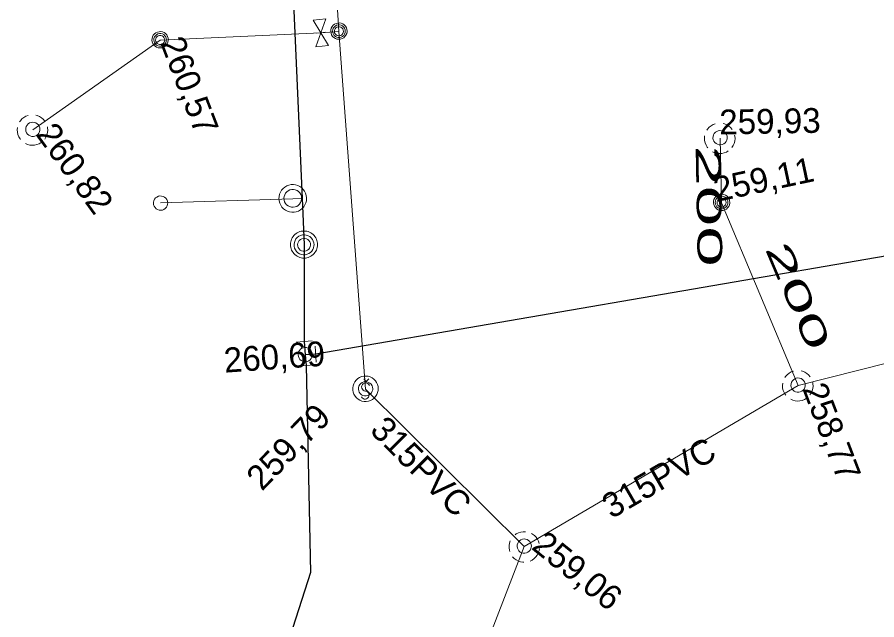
# Model space of a CAD drawing. Extents: x -732096 to -731933, y -1048703 to -1047964.
# Drawn here: x -732042.72 to -732014.98, y -1048007.32 to -1047987.86 of the extents above; entities that cross this region are included whole.
import ezdxf

# ---------------------------------------------------------------- set-up
doc = ezdxf.new("R2010")
doc.units = 0
doc.header["$LTSCALE"] = 0.32
doc.layers.add('1', color=7, linetype='Continuous')
for name, color, linetype, lineweight in [('18', 7, 'Continuous', 13), ('20', 7, 'Continuous', 13), ('21', 7, 'Continuous', 13), ('49', 7, 'Continuous', 13), ('50', 7, 'Continuous', 13), ('8', 7, 'Continuous', 13)]:
    doc.layers.add(name, color=color, linetype=linetype, lineweight=lineweight)

msp = doc.modelspace()

# ---------------------------------------------------------------- linework, layer by layer
at = {"layer": '18'}
for q in [(-732033.071, -1047988.374), (-732032.773, -1047988.343)]:
    msp.add_line((-732032.922, -1047988.359), q, dxfattribs=at)
for points in [[(-732032.671, -1047988.769), (-732033.173, -1047987.949), (-732032.761, -1047987.906), (-732033.083, -1047988.812)], [(-732032.076, -1047988.307), (-732032.081, -1047988.251), (-732032.098, -1047988.198), (-732032.127, -1047988.149), (-732032.166, -1047988.108), (-732032.212, -1047988.076), (-732032.264, -1047988.054), (-732032.319, -1047988.043), (-732032.375, -1047988.045), (-732032.429, -1047988.058), (-732032.48, -1047988.083), (-732032.525, -1047988.118), (-732032.561, -1047988.161), (-732032.586, -1047988.211), (-732032.601, -1047988.266), (-732032.603, -1047988.322), (-732032.595, -1047988.377), (-732032.574, -1047988.43), (-732032.543, -1047988.476), (-732032.502, -1047988.515), (-732032.455, -1047988.545), (-732032.402, -1047988.564), (-732032.346, -1047988.571), (-732032.289, -1047988.567), (-732032.235, -1047988.55), (-732032.186, -1047988.523), (-732032.145, -1047988.485), (-732032.112, -1047988.44), (-732032.088, -1047988.389), (-732032.076, -1047988.334)], [(-732032.135, -1047988.31), (-732032.141, -1047988.261), (-732032.159, -1047988.215), (-732032.186, -1047988.174), (-732032.223, -1047988.141), (-732032.267, -1047988.119), (-732032.316, -1047988.107), (-732032.365, -1047988.107), (-732032.413, -1047988.119), (-732032.456, -1047988.142), (-732032.494, -1047988.175), (-732032.522, -1047988.216), (-732032.539, -1047988.263), (-732032.544, -1047988.312), (-732032.538, -1047988.361), (-732032.52, -1047988.407), (-732032.492, -1047988.447), (-732032.455, -1047988.48), (-732032.411, -1047988.502), (-732032.362, -1047988.514), (-732032.313, -1047988.513), (-732032.265, -1047988.501), (-732032.222, -1047988.477), (-732032.184, -1047988.444), (-732032.157, -1047988.403), (-732032.141, -1047988.356)], [(-732032.194, -1047988.314), (-732032.2, -1047988.272), (-732032.217, -1047988.234), (-732032.245, -1047988.203), (-732032.279, -1047988.18), (-732032.32, -1047988.169), (-732032.362, -1047988.169), (-732032.402, -1047988.181), (-732032.436, -1047988.204), (-732032.463, -1047988.236), (-732032.48, -1047988.274), (-732032.485, -1047988.315), (-732032.48, -1047988.357), (-732032.462, -1047988.394), (-732032.434, -1047988.426), (-732032.397, -1047988.448), (-732032.358, -1047988.459), (-732032.316, -1047988.458), (-732032.276, -1047988.445), (-732032.242, -1047988.422), (-732032.215, -1047988.389), (-732032.199, -1047988.351)], [(-732037.845, -1047988.587), (-732037.851, -1047988.531), (-732037.868, -1047988.478), (-732037.897, -1047988.429), (-732037.935, -1047988.388), (-732037.981, -1047988.356), (-732038.033, -1047988.334), (-732038.088, -1047988.323), (-732038.144, -1047988.325), (-732038.199, -1047988.338), (-732038.25, -1047988.363), (-732038.294, -1047988.398), (-732038.33, -1047988.441), (-732038.355, -1047988.491), (-732038.37, -1047988.546), (-732038.373, -1047988.602), (-732038.364, -1047988.657), (-732038.343, -1047988.71), (-732038.312, -1047988.756), (-732038.272, -1047988.795), (-732038.224, -1047988.825), (-732038.171, -1047988.844), (-732038.115, -1047988.851), (-732038.059, -1047988.847), (-732038.005, -1047988.83), (-732037.956, -1047988.803), (-732037.914, -1047988.765), (-732037.881, -1047988.72), (-732037.858, -1047988.669), (-732037.846, -1047988.614)], [(-732037.904, -1047988.59), (-732037.91, -1047988.541), (-732037.928, -1047988.495), (-732037.956, -1047988.454), (-732037.993, -1047988.421), (-732038.037, -1047988.399), (-732038.085, -1047988.387), (-732038.134, -1047988.387), (-732038.182, -1047988.399), (-732038.226, -1047988.422), (-732038.263, -1047988.455), (-732038.291, -1047988.496), (-732038.308, -1047988.543), (-732038.314, -1047988.592), (-732038.307, -1047988.641), (-732038.289, -1047988.687), (-732038.261, -1047988.727), (-732038.224, -1047988.76), (-732038.18, -1047988.782), (-732038.131, -1047988.794), (-732038.082, -1047988.793), (-732038.034, -1047988.781), (-732037.991, -1047988.757), (-732037.954, -1047988.724), (-732037.926, -1047988.683), (-732037.91, -1047988.636)], [(-732037.963, -1047988.594), (-732037.969, -1047988.552), (-732037.986, -1047988.514), (-732038.014, -1047988.483), (-732038.049, -1047988.46), (-732038.089, -1047988.449), (-732038.131, -1047988.449), (-732038.171, -1047988.461), (-732038.206, -1047988.484), (-732038.233, -1047988.516), (-732038.25, -1047988.554), (-732038.255, -1047988.595), (-732038.249, -1047988.637), (-732038.231, -1047988.674), (-732038.203, -1047988.706), (-732038.167, -1047988.728), (-732038.127, -1047988.739), (-732038.085, -1047988.738), (-732038.045, -1047988.725), (-732038.011, -1047988.702), (-732037.984, -1047988.669), (-732037.968, -1047988.631)], [(-732041.988, -1047991.479), (-732041.994, -1047991.427), (-732042.012, -1047991.377), (-732042.04, -1047991.333), (-732042.078, -1047991.296), (-732042.123, -1047991.269), (-732042.173, -1047991.253), (-732042.225, -1047991.248), (-732042.277, -1047991.255), (-732042.326, -1047991.274), (-732042.37, -1047991.304), (-732042.405, -1047991.343), (-732042.431, -1047991.388), (-732042.446, -1047991.439), (-732042.449, -1047991.491), (-732042.441, -1047991.543), (-732042.42, -1047991.591), (-732042.39, -1047991.634), (-732042.35, -1047991.669), (-732042.304, -1047991.693), (-732042.253, -1047991.707), (-732042.201, -1047991.709), (-732042.149, -1047991.699), (-732042.101, -1047991.677), (-732042.059, -1047991.645), (-732042.026, -1047991.605), (-732042.002, -1047991.558), (-732041.99, -1047991.507)], [(-732019.808, -1047991.749), (-732019.814, -1047991.697), (-732019.831, -1047991.647), (-732019.86, -1047991.603), (-732019.898, -1047991.566), (-732019.943, -1047991.539), (-732019.993, -1047991.523), (-732020.045, -1047991.518), (-732020.097, -1047991.525), (-732020.146, -1047991.544), (-732020.19, -1047991.574), (-732020.225, -1047991.613), (-732020.251, -1047991.658), (-732020.266, -1047991.709), (-732020.269, -1047991.761), (-732020.261, -1047991.813), (-732020.24, -1047991.861), (-732020.21, -1047991.904), (-732020.17, -1047991.939), (-732020.124, -1047991.963), (-732020.073, -1047991.977), (-732020.021, -1047991.979), (-732019.969, -1047991.969), (-732019.921, -1047991.947), (-732019.879, -1047991.915), (-732019.846, -1047991.875), (-732019.822, -1047991.828), (-732019.809, -1047991.777)], [(-732019.725, -1047993.837), (-732019.73, -1047993.781), (-732019.747, -1047993.728), (-732019.776, -1047993.679), (-732019.815, -1047993.638), (-732019.86, -1047993.606), (-732019.913, -1047993.584), (-732019.968, -1047993.573), (-732020.024, -1047993.575), (-732020.078, -1047993.588), (-732020.129, -1047993.613), (-732020.174, -1047993.648), (-732020.21, -1047993.691), (-732020.235, -1047993.741), (-732020.25, -1047993.796), (-732020.252, -1047993.852), (-732020.244, -1047993.907), (-732020.223, -1047993.96), (-732020.191, -1047994.006), (-732020.151, -1047994.045), (-732020.103, -1047994.075), (-732020.051, -1047994.094), (-732019.995, -1047994.101), (-732019.938, -1047994.097), (-732019.884, -1047994.08), (-732019.835, -1047994.053), (-732019.794, -1047994.015), (-732019.761, -1047993.97), (-732019.737, -1047993.919), (-732019.725, -1047993.864)], [(-732019.784, -1047993.84), (-732019.789, -1047993.791), (-732019.808, -1047993.745), (-732019.835, -1047993.704), (-732019.872, -1047993.671), (-732019.916, -1047993.649), (-732019.965, -1047993.637), (-732020.014, -1047993.637), (-732020.061, -1047993.649), (-732020.105, -1047993.672), (-732020.142, -1047993.705), (-732020.171, -1047993.746), (-732020.188, -1047993.793), (-732020.193, -1047993.842), (-732020.186, -1047993.891), (-732020.169, -1047993.937), (-732020.141, -1047993.977), (-732020.103, -1047994.01), (-732020.059, -1047994.032), (-732020.011, -1047994.044), (-732019.962, -1047994.043), (-732019.914, -1047994.031), (-732019.87, -1047994.007), (-732019.833, -1047993.974), (-732019.806, -1047993.933), (-732019.789, -1047993.886)], [(-732019.843, -1047993.844), (-732019.848, -1047993.802), (-732019.865, -1047993.764), (-732019.894, -1047993.733), (-732019.928, -1047993.71), (-732019.968, -1047993.699), (-732020.011, -1047993.699), (-732020.051, -1047993.711), (-732020.085, -1047993.734), (-732020.112, -1047993.766), (-732020.129, -1047993.804), (-732020.134, -1047993.845), (-732020.129, -1047993.887), (-732020.11, -1047993.924), (-732020.083, -1047993.956), (-732020.046, -1047993.978), (-732020.007, -1047993.989), (-732019.965, -1047993.988), (-732019.924, -1047993.975), (-732019.891, -1047993.952), (-732019.864, -1047993.919), (-732019.848, -1047993.881)], [(-732031.071, -1047999.857), (-732031.078, -1047999.787), (-732031.096, -1047999.719), (-732031.125, -1047999.655), (-732031.164, -1047999.597), (-732031.213, -1047999.547), (-732031.27, -1047999.505), (-732031.333, -1047999.474), (-732031.4, -1047999.454), (-732031.47, -1047999.445), (-732031.54, -1047999.449), (-732031.608, -1047999.464), (-732031.673, -1047999.491), (-732031.733, -1047999.529), (-732031.785, -1047999.576), (-732031.828, -1047999.631), (-732031.862, -1047999.693), (-732031.884, -1047999.76), (-732031.895, -1047999.829), (-732031.892, -1047999.899), (-732031.88, -1047999.968), (-732031.856, -1048000.034), (-732031.82, -1048000.095), (-732031.775, -1048000.148), (-732031.721, -1048000.194), (-732031.661, -1048000.229), (-732031.595, -1048000.254), (-732031.526, -1048000.267), (-732031.456, -1048000.268), (-732031.386, -1048000.257), (-732031.32, -1048000.235), (-732031.258, -1048000.201), (-732031.203, -1048000.158), (-732031.156, -1048000.106), (-732031.118, -1048000.046), (-732031.091, -1047999.981), (-732031.076, -1047999.913)], [(-732017.289, -1047999.739), (-732017.295, -1047999.687), (-732017.313, -1047999.637), (-732017.341, -1047999.593), (-732017.379, -1047999.556), (-732017.424, -1047999.529), (-732017.474, -1047999.513), (-732017.526, -1047999.508), (-732017.578, -1047999.515), (-732017.627, -1047999.534), (-732017.671, -1047999.564), (-732017.706, -1047999.603), (-732017.732, -1047999.648), (-732017.747, -1047999.699), (-732017.75, -1047999.751), (-732017.742, -1047999.803), (-732017.721, -1047999.851), (-732017.691, -1047999.894), (-732017.651, -1047999.929), (-732017.605, -1047999.953), (-732017.554, -1047999.967), (-732017.502, -1047999.969), (-732017.45, -1047999.959), (-732017.402, -1047999.937), (-732017.36, -1047999.905), (-732017.327, -1047999.865), (-732017.303, -1047999.818), (-732017.291, -1047999.767)], [(-732031.249, -1047999.859), (-732031.255, -1047999.807), (-732031.272, -1047999.757), (-732031.301, -1047999.713), (-732031.339, -1047999.676), (-732031.384, -1047999.649), (-732031.434, -1047999.633), (-732031.486, -1047999.628), (-732031.538, -1047999.635), (-732031.587, -1047999.654), (-732031.63, -1047999.684), (-732031.666, -1047999.723), (-732031.692, -1047999.768), (-732031.706, -1047999.819), (-732031.71, -1047999.871), (-732031.701, -1047999.923), (-732031.681, -1047999.971), (-732031.651, -1048000.014), (-732031.611, -1048000.049), (-732031.565, -1048000.073), (-732031.514, -1048000.087), (-732031.462, -1048000.089), (-732031.41, -1048000.079), (-732031.362, -1048000.057), (-732031.32, -1048000.025), (-732031.287, -1047999.985), (-732031.263, -1047999.938), (-732031.25, -1047999.887)], [(-732026.128, -1048004.939), (-732026.134, -1048004.887), (-732026.152, -1048004.837), (-732026.18, -1048004.793), (-732026.218, -1048004.756), (-732026.263, -1048004.729), (-732026.313, -1048004.713), (-732026.365, -1048004.708), (-732026.417, -1048004.715), (-732026.466, -1048004.734), (-732026.51, -1048004.764), (-732026.545, -1048004.803), (-732026.571, -1048004.848), (-732026.586, -1048004.899), (-732026.589, -1048004.951), (-732026.581, -1048005.003), (-732026.56, -1048005.051), (-732026.53, -1048005.094), (-732026.49, -1048005.129), (-732026.444, -1048005.153), (-732026.393, -1048005.167), (-732026.341, -1048005.169), (-732026.289, -1048005.159), (-732026.241, -1048005.137), (-732026.199, -1048005.105), (-732026.166, -1048005.065), (-732026.142, -1048005.018), (-732026.13, -1048004.967)]]:
    msp.add_lwpolyline(points, close=True, dxfattribs=at)
for points in [[(-732042.372, -1047991.027), (-732042.443, -1047991.055), (-732042.51, -1047991.094), (-732042.57, -1047991.142), (-732042.621, -1047991.199), (-732042.645, -1047991.233)], [(-732041.831, -1047991.21), (-732041.881, -1047991.152), (-732041.939, -1047991.102), (-732042.004, -1047991.061), (-732042.075, -1047991.032), (-732042.124, -1047991.018)], [(-732042.717, -1047991.419), (-732042.723, -1047991.496), (-732042.718, -1047991.573), (-732042.701, -1047991.648), (-732042.672, -1047991.719), (-732042.632, -1047991.785), (-732042.616, -1047991.807)], [(-732041.836, -1047991.796), (-732041.795, -1047991.731), (-732041.764, -1047991.661), (-732041.745, -1047991.586), (-732041.737, -1047991.51), (-732041.742, -1047991.433), (-732041.748, -1047991.398)], [(-732020.192, -1047991.297), (-732020.263, -1047991.325), (-732020.33, -1047991.364), (-732020.39, -1047991.412), (-732020.441, -1047991.469), (-732020.465, -1047991.503)], [(-732019.651, -1047991.48), (-732019.701, -1047991.422), (-732019.759, -1047991.372), (-732019.824, -1047991.331), (-732019.895, -1047991.302), (-732019.944, -1047991.288)], [(-732020.537, -1047991.689), (-732020.543, -1047991.766), (-732020.538, -1047991.843), (-732020.521, -1047991.918), (-732020.492, -1047991.989), (-732020.451, -1047992.055), (-732020.436, -1047992.077)], [(-732019.656, -1047992.066), (-732019.615, -1047992.001), (-732019.584, -1047991.931), (-732019.565, -1047991.856), (-732019.557, -1047991.78), (-732019.562, -1047991.703), (-732019.568, -1047991.668)], [(-732042.459, -1047991.936), (-732042.389, -1047991.967), (-732042.314, -1047991.986), (-732042.238, -1047991.993), (-732042.161, -1047991.988), (-732042.086, -1047991.971), (-732042.014, -1047991.943), (-732041.954, -1047991.908)], [(-732020.279, -1047992.206), (-732020.209, -1047992.237), (-732020.134, -1047992.256), (-732020.058, -1047992.263), (-732019.981, -1047992.258), (-732019.906, -1047992.241), (-732019.834, -1047992.213), (-732019.774, -1047992.178)], [(-732017.673, -1047999.287), (-732017.744, -1047999.315), (-732017.811, -1047999.354), (-732017.871, -1047999.402), (-732017.922, -1047999.459), (-732017.946, -1047999.493)], [(-732017.132, -1047999.47), (-732017.182, -1047999.412), (-732017.24, -1047999.362), (-732017.305, -1047999.321), (-732017.376, -1047999.292), (-732017.425, -1047999.278)], [(-732031.532, -1047999.537), (-732031.462, -1047999.624), (-732031.373, -1047999.535)], [(-732031.355, -1047999.749), (-732031.375, -1047999.715), (-732031.405, -1047999.689), (-732031.441, -1047999.673), (-732031.48, -1047999.669), (-732031.519, -1047999.676), (-732031.553, -1047999.695), (-732031.581, -1047999.723), (-732031.598, -1047999.758), (-732031.606, -1047999.797), (-732031.6, -1047999.836), (-732031.583, -1047999.871), (-732031.557, -1047999.9), (-732031.522, -1047999.92), (-732031.483, -1047999.929)], [(-732018.018, -1047999.679), (-732018.024, -1047999.756), (-732018.019, -1047999.833), (-732018.002, -1047999.908), (-732017.973, -1047999.979), (-732017.933, -1048000.045), (-732017.917, -1048000.067)], [(-732017.137, -1048000.056), (-732017.096, -1047999.991), (-732017.065, -1047999.921), (-732017.046, -1047999.846), (-732017.038, -1047999.77), (-732017.043, -1047999.693), (-732017.049, -1047999.658)], [(-732031.615, -1048000.116), (-732031.593, -1048000.149), (-732031.562, -1048000.174), (-732031.525, -1048000.188), (-732031.485, -1048000.191), (-732031.446, -1048000.182), (-732031.413, -1048000.162), (-732031.386, -1048000.132), (-732031.37, -1048000.096), (-732031.364, -1048000.057), (-732031.37, -1048000.018), (-732031.39, -1047999.983), (-732031.417, -1047999.955), (-732031.451, -1047999.936), (-732031.485, -1047999.929)], [(-732017.76, -1048000.196), (-732017.69, -1048000.227), (-732017.615, -1048000.246), (-732017.539, -1048000.253), (-732017.462, -1048000.248), (-732017.387, -1048000.231), (-732017.315, -1048000.203), (-732017.255, -1048000.168)], [(-732026.322, -1048004.473), (-732026.398, -1048004.474), (-732026.474, -1048004.486), (-732026.547, -1048004.509), (-732026.615, -1048004.544), (-732026.657, -1048004.573)], [(-732025.877, -1048004.855), (-732025.9, -1048004.781), (-732025.934, -1048004.713), (-732025.979, -1048004.65), (-732026.032, -1048004.594), (-732026.094, -1048004.549), (-732026.124, -1048004.531)], [(-732026.811, -1048004.768), (-732026.835, -1048004.84), (-732026.848, -1048004.917), (-732026.85, -1048004.993), (-732026.84, -1048005.069), (-732026.829, -1048005.109)], [(-732026.172, -1048005.421), (-732026.103, -1048005.387), (-732026.04, -1048005.342), (-732025.986, -1048005.289), (-732025.94, -1048005.227), (-732025.905, -1048005.159), (-732025.88, -1048005.086), (-732025.868, -1048005.017)], [(-732026.734, -1048005.284), (-732026.679, -1048005.339), (-732026.617, -1048005.385), (-732026.548, -1048005.42), (-732026.475, -1048005.444), (-732026.399, -1048005.456), (-732026.372, -1048005.458)]]:
    msp.add_lwpolyline(points, dxfattribs=at)
at = {"layer": '20'}
for points in [[(-732017.52, -1047999.75), (-732004.701, -1047996.513), (-731999.955, -1047995.314)], [(-732017.52, -1047999.75), (-732004.701, -1047996.513), (-731999.955, -1047995.314)], [(-732031.48, -1047999.87), (-732026.359, -1048004.95), (-732017.52, -1047999.75)], [(-732031.48, -1047999.87), (-732026.359, -1048004.95), (-732017.52, -1047999.75)], [(-732035.469, -1048028.56), (-732035.152, -1048027.738), (-732032.882, -1048021.854), (-732030.648, -1048016.063), (-732026.359, -1048004.95)], [(-732035.469, -1048028.56), (-732035.152, -1048027.738), (-732032.882, -1048021.854), (-732030.648, -1048016.063), (-732026.359, -1048004.95)]]:
    msp.add_lwpolyline(points, dxfattribs=at)
at = {"layer": '21'}
msp.add_lwpolyline([(-732033.777, -1047967.353), (-732033.19, -1047974.34), (-732032.34, -1047988.32), (-732031.48, -1047999.87)], dxfattribs=at)
msp.add_lwpolyline([(-732033.777, -1047967.353), (-732033.19, -1047974.34), (-732032.34, -1047988.32), (-732031.48, -1047999.87)], dxfattribs=at)
at = {"layer": '49'}
for p, q in [((-732020.039, -1047991.76), (-732019.989, -1047993.85)), ((-732020.039, -1047991.76), (-732019.989, -1047993.85)), ((-732019.989, -1047993.85), (-732017.52, -1047999.75)), ((-732019.989, -1047993.85), (-732017.52, -1047999.75))]:
    msp.add_line(p, q, dxfattribs=at)
at = {"layer": '50'}
for p, q in [((-732038.109, -1047988.6), (-732032.92, -1047988.36)), ((-732032.92, -1047988.36), (-732032.34, -1047988.32)), ((-732042.219, -1047991.49), (-732038.109, -1047988.6))]:
    msp.add_line(p, q, dxfattribs=at)
msp.add_lwpolyline([(-732042.219, -1047991.49), (-732038.109, -1047988.6), (-732032.92, -1047988.36), (-732032.34, -1047988.32)], dxfattribs=at)
at = {"layer": '8'}
for p, q in [((-732033.829, -1047993.72), (-732038.096, -1047993.852)), ((-732033.525, -1047993.715), (-732033.829, -1047993.72)), ((-732033.718, -1047998.35), (-732033.203, -1047998.31)), ((-732033.108, -1047998.48), (-732033.069, -1047998.995)), ((-732033.14, -1047999.088), (-732033.655, -1047999.131))]:
    msp.add_line(p, q, dxfattribs=at)
at = {"layer": '8', "lineweight": 25}
for p, q in [((-732033.46, -1047995.21), (-732033.46, -1047998.33)), ((-732014.03, -1047995.459), (-732033.089, -1047998.739)), ((-732033.46, -1047998.33), (-732033.427, -1047998.765)), ((-732033.089, -1047998.739), (-732033.427, -1047998.765)), ((-732033.427, -1047998.765), (-732033.399, -1047999.11))]:
    msp.add_line(p, q, dxfattribs=at)
for points in [[(-732034.674, -1047967.446), (-732034.659, -1047967.6), (-732034.05, -1047981.809), (-732033.525, -1047993.715), (-732033.46, -1047995.21)], [(-732033.399, -1047999.11), (-732033.26, -1048005.79), (-732035.475, -1048012.689), (-732038.309, -1048021.518), (-732038.774, -1048026.833), (-732038.94, -1048028.735), (-732039.3, -1048037.077)]]:
    msp.add_lwpolyline(points, dxfattribs=at)
at = {"layer": '8'}
for points in [[(-732033.383, -1047993.687), (-732033.392, -1047993.614), (-732033.414, -1047993.544), (-732033.446, -1047993.479), (-732033.489, -1047993.42), (-732033.541, -1047993.367), (-732033.6, -1047993.325), (-732033.666, -1047993.293), (-732033.736, -1047993.272), (-732033.808, -1047993.262), (-732033.882, -1047993.265), (-732033.954, -1047993.28), (-732034.022, -1047993.306), (-732034.085, -1047993.342), (-732034.141, -1047993.389), (-732034.19, -1047993.445), (-732034.228, -1047993.507), (-732034.255, -1047993.575), (-732034.272, -1047993.646), (-732034.276, -1047993.719), (-732034.268, -1047993.792), (-732034.249, -1047993.862), (-732034.219, -1047993.929), (-732034.177, -1047993.99), (-732034.127, -1047994.042), (-732034.068, -1047994.086), (-732034.004, -1047994.12), (-732033.934, -1047994.144), (-732033.862, -1047994.155), (-732033.789, -1047994.155), (-732033.716, -1047994.142), (-732033.647, -1047994.117), (-732033.583, -1047994.082), (-732033.525, -1047994.037), (-732033.476, -1047993.984), (-732033.436, -1047993.922), (-732033.406, -1047993.855), (-732033.389, -1047993.784), (-732033.382, -1047993.712)], [(-732033.543, -1047993.695), (-732033.552, -1047993.637), (-732033.573, -1047993.582), (-732033.604, -1047993.533), (-732033.645, -1047993.491), (-732033.692, -1047993.457), (-732033.747, -1047993.435), (-732033.804, -1047993.423), (-732033.863, -1047993.424), (-732033.92, -1047993.437), (-732033.974, -1047993.462), (-732034.021, -1047993.496), (-732034.06, -1047993.539), (-732034.089, -1047993.59), (-732034.109, -1047993.646), (-732034.116, -1047993.703), (-732034.111, -1047993.762), (-732034.094, -1047993.818), (-732034.066, -1047993.87), (-732034.028, -1047993.914), (-732033.982, -1047993.951), (-732033.93, -1047993.976), (-732033.873, -1047993.992), (-732033.815, -1047993.995), (-732033.757, -1047993.986), (-732033.702, -1047993.966), (-732033.653, -1047993.934), (-732033.611, -1047993.893), (-732033.578, -1047993.846), (-732033.556, -1047993.791), (-732033.544, -1047993.734)], [(-732038.326, -1047993.862), (-732038.32, -1047993.914), (-732038.302, -1047993.964), (-732038.274, -1047994.008), (-732038.235, -1047994.045), (-732038.19, -1047994.072), (-732038.14, -1047994.087), (-732038.088, -1047994.092), (-732038.036, -1047994.085), (-732037.987, -1047994.065), (-732037.943, -1047994.035), (-732037.909, -1047993.996), (-732037.883, -1047993.951), (-732037.868, -1047993.9), (-732037.866, -1047993.848), (-732037.874, -1047993.796), (-732037.895, -1047993.748), (-732037.925, -1047993.705), (-732037.966, -1047993.67), (-732038.012, -1047993.646), (-732038.063, -1047993.633), (-732038.115, -1047993.631), (-732038.167, -1047993.641), (-732038.215, -1047993.664), (-732038.256, -1047993.696), (-732038.289, -1047993.736), (-732038.313, -1047993.783), (-732038.325, -1047993.834)], [(-732033.142, -1047995.207), (-732033.149, -1047995.146), (-732033.167, -1047995.086), (-732033.196, -1047995.031), (-732033.235, -1047994.983), (-732033.282, -1047994.943), (-732033.336, -1047994.913), (-732033.395, -1047994.893), (-732033.456, -1047994.886), (-732033.519, -1047994.89), (-732033.578, -1047994.906), (-732033.634, -1047994.934), (-732033.684, -1047994.971), (-732033.725, -1047995.018), (-732033.757, -1047995.071), (-732033.777, -1047995.13), (-732033.787, -1047995.191), (-732033.784, -1047995.253), (-732033.769, -1047995.313), (-732033.743, -1047995.37), (-732033.706, -1047995.42), (-732033.661, -1047995.463), (-732033.608, -1047995.495), (-732033.551, -1047995.518), (-732033.49, -1047995.528), (-732033.428, -1047995.527), (-732033.367, -1047995.514), (-732033.309, -1047995.489), (-732033.259, -1047995.454), (-732033.215, -1047995.41), (-732033.181, -1047995.358), (-732033.157, -1047995.301), (-732033.145, -1047995.24)], [(-732033.257, -1047995.207), (-732033.262, -1047995.158), (-732033.279, -1047995.111), (-732033.308, -1047995.07), (-732033.346, -1047995.037), (-732033.39, -1047995.013), (-732033.438, -1047995.001), (-732033.488, -1047995), (-732033.536, -1047995.012), (-732033.581, -1047995.034), (-732033.619, -1047995.067), (-732033.647, -1047995.107), (-732033.667, -1047995.154), (-732033.674, -1047995.203), (-732033.669, -1047995.253), (-732033.652, -1047995.3), (-732033.625, -1047995.342), (-732033.588, -1047995.376), (-732033.544, -1047995.4), (-732033.497, -1047995.414), (-732033.446, -1047995.415), (-732033.397, -1047995.405), (-732033.353, -1047995.383), (-732033.314, -1047995.351), (-732033.284, -1047995.312), (-732033.265, -1047995.266), (-732033.257, -1047995.216)], [(-732033.196, -1047998.754), (-732033.202, -1047998.702), (-732033.22, -1047998.652), (-732033.248, -1047998.608), (-732033.286, -1047998.571), (-732033.331, -1047998.544), (-732033.381, -1047998.528), (-732033.433, -1047998.523), (-732033.485, -1047998.53), (-732033.534, -1047998.549), (-732033.578, -1047998.579), (-732033.613, -1047998.618), (-732033.639, -1047998.663), (-732033.654, -1047998.714), (-732033.657, -1047998.766), (-732033.649, -1047998.818), (-732033.628, -1047998.866), (-732033.598, -1047998.909), (-732033.558, -1047998.944), (-732033.512, -1047998.968), (-732033.461, -1047998.982), (-732033.409, -1047998.984), (-732033.357, -1047998.974), (-732033.309, -1047998.952), (-732033.267, -1047998.92), (-732033.234, -1047998.88), (-732033.21, -1047998.833), (-732033.198, -1047998.782)]]:
    msp.add_lwpolyline(points, close=True, dxfattribs=at)
msp.add_lwpolyline([(-732033.029, -1047995.199), (-732033.032, -1047995.154), (-732033.039, -1047995.109), (-732033.051, -1047995.064), (-732033.066, -1047995.022), (-732033.088, -1047994.981), (-732033.113, -1047994.942), (-732033.142, -1047994.907), (-732033.174, -1047994.874), (-732033.21, -1047994.846), (-732033.247, -1047994.821), (-732033.289, -1047994.8), (-732033.331, -1047994.783), (-732033.375, -1047994.771), (-732033.421, -1047994.764), (-732033.467, -1047994.762), (-732033.512, -1047994.764), (-732033.558, -1047994.771), (-732033.602, -1047994.783), (-732033.645, -1047994.8), (-732033.686, -1047994.821), (-732033.723, -1047994.846), (-732033.76, -1047994.874), (-732033.792, -1047994.907), (-732033.821, -1047994.942), (-732033.846, -1047994.981), (-732033.867, -1047995.022), (-732033.882, -1047995.064), (-732033.895, -1047995.109), (-732033.902, -1047995.154), (-732033.904, -1047995.2), (-732033.902, -1047995.245), (-732033.895, -1047995.29), (-732033.882, -1047995.335), (-732033.867, -1047995.377), (-732033.846, -1047995.418), (-732033.821, -1047995.457), (-732033.792, -1047995.492), (-732033.76, -1047995.525), (-732033.723, -1047995.553), (-732033.686, -1047995.578), (-732033.645, -1047995.599), (-732033.602, -1047995.616), (-732033.558, -1047995.627), (-732033.512, -1047995.635), (-732033.467, -1047995.637), (-732033.421, -1047995.635), (-732033.375, -1047995.627), (-732033.331, -1047995.616), (-732033.289, -1047995.599), (-732033.247, -1047995.578), (-732033.21, -1047995.553), (-732033.174, -1047995.525), (-732033.142, -1047995.492), (-732033.113, -1047995.457), (-732033.088, -1047995.418), (-732033.066, -1047995.377), (-732033.051, -1047995.335), (-732033.039, -1047995.29), (-732033.032, -1047995.245), (-732033.029, -1047995.2)], dxfattribs=at)

# ---------------------------------------------------------------- texts
at = {"layer": '1'}
for s, rotation, p in [('260,57', 291, (-732038.118, -1047988.673)), ('259,93', 1, (-732020.058, -1047991.645)), ('260,82', 306, (-732042.142, -1047991.647)), ('259,11', 12, (-732020.151, -1047993.825)), ('260,69', 4, (-732036.026, -1047999.338)), ('258,77', 291, (-732017.388, -1047999.856)), ('259,79', 46, (-732034.823, -1048003.183)), ('315PVC', 315, (-732031.374, -1048001.236)), ('315PVC', 30, (-732023.542, -1048004.071)), ('259,06', 321, (-732026.16, -1048005.007))]:
    msp.add_text(s, height=0.8, rotation=rotation, dxfattribs=at).set_placement(p)
for rotation, width, p in [(271, 2.2, (-732020.828, -1047991.997)), (293, 2.05, (-732018.603, -1047995.325))]:
    msp.add_text('200 ', height=0.8, rotation=rotation, dxfattribs=dict(at, width=width)).set_placement(p)

doc.saveas('drawing.dxf')
